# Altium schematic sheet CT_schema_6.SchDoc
size 368 x 245 mm
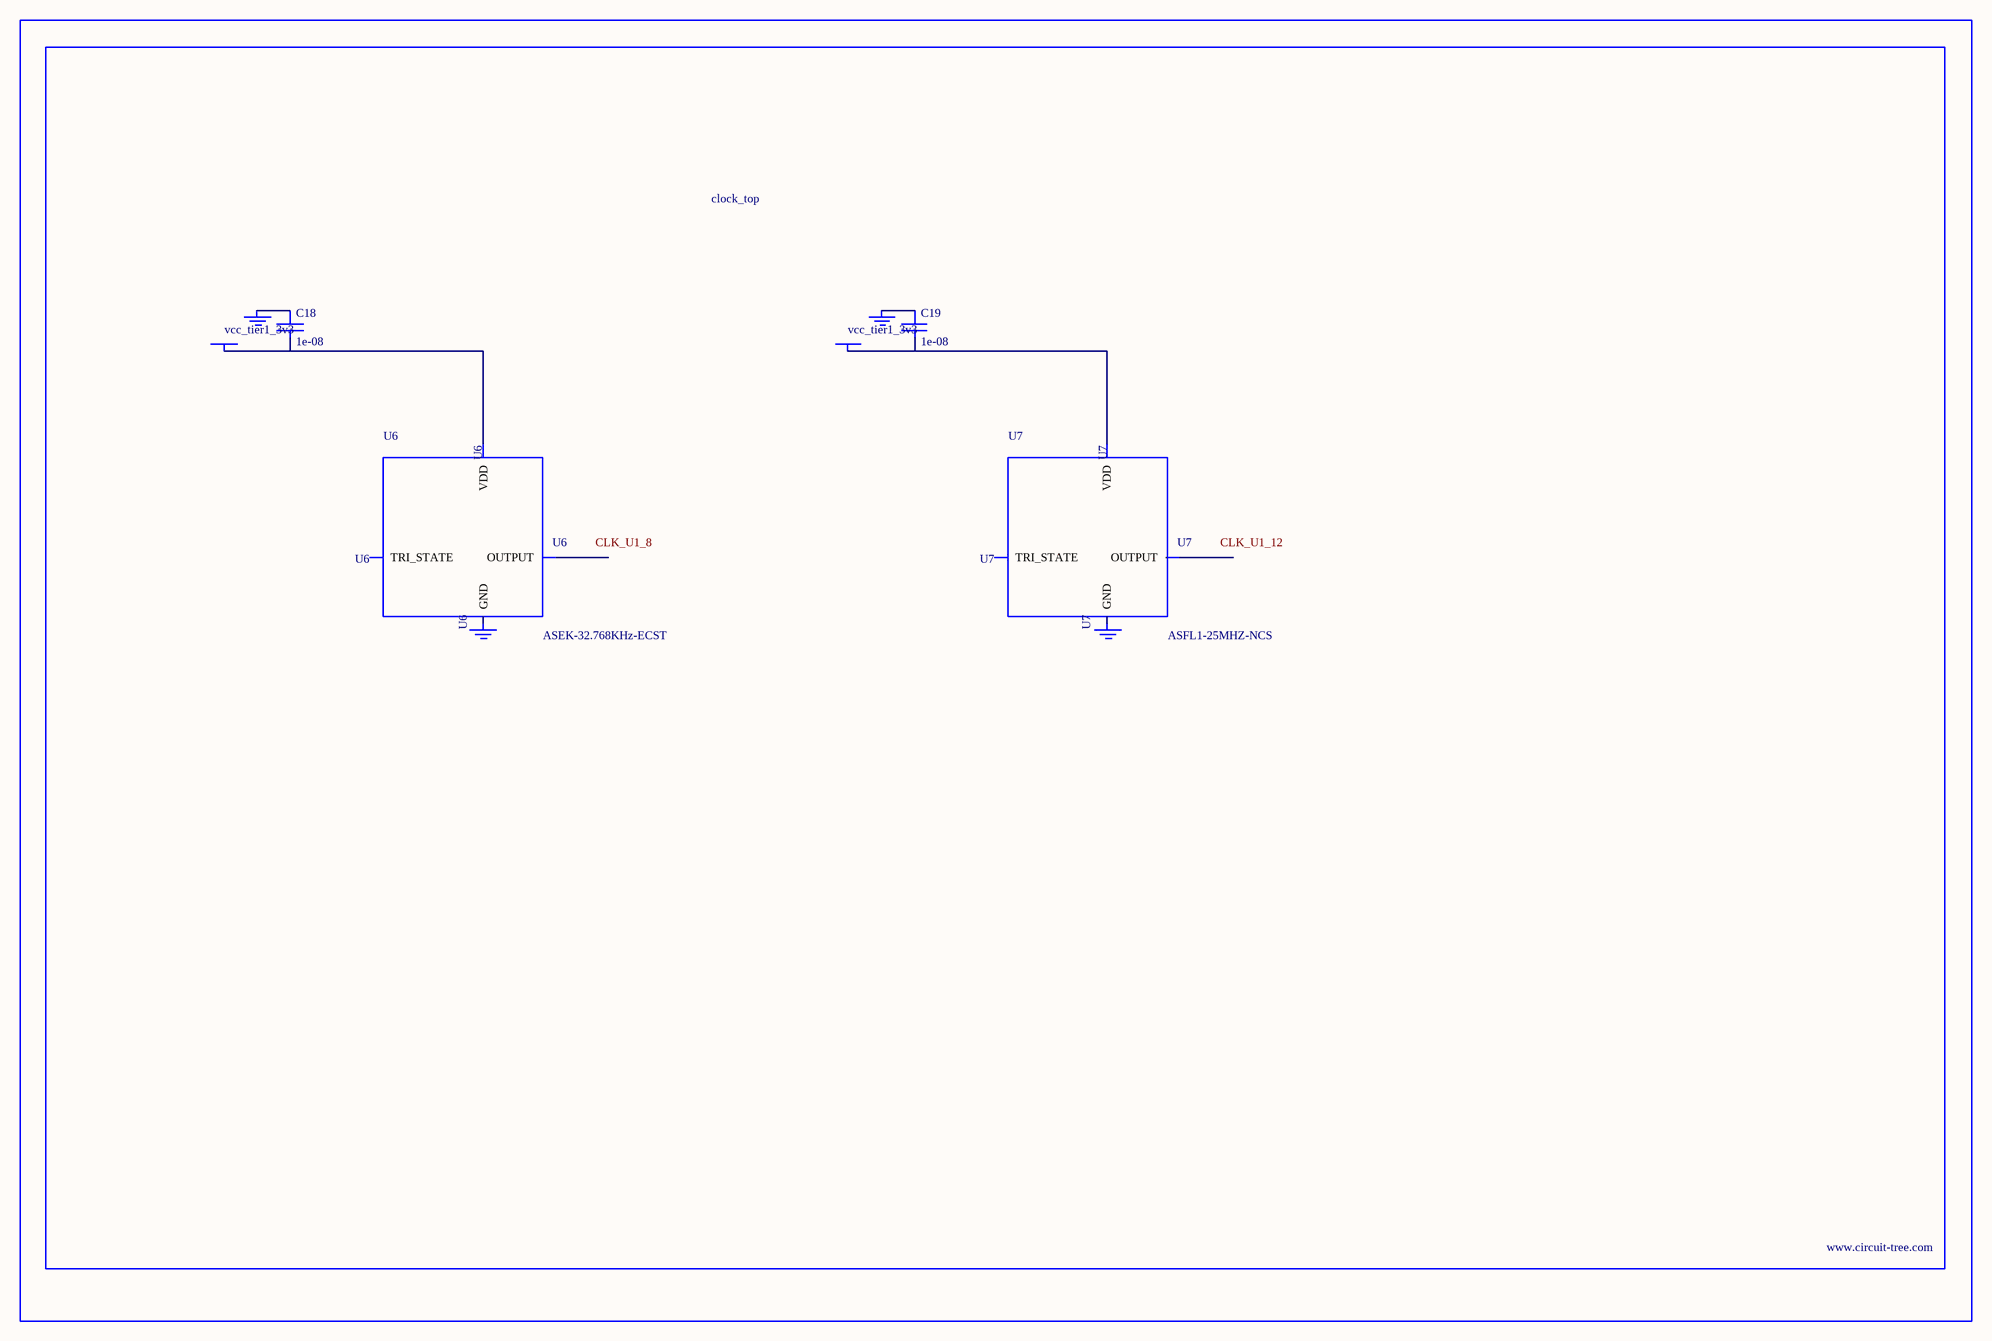
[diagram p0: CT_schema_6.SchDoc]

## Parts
BORDER5  (no value)
C18  1e-08  [C0402]
C19  1e-08  [C0402]
GND_INSTANCE_5_0  (no value)
GND_INSTANCE_5_1  (no value)
GND_INSTANCE_5_2  (no value)
GND_INSTANCE_5_3  (no value)
POWER_INSTANCE_5_0  vcc_tier1_3v3
POWER_INSTANCE_5_1  vcc_tier1_3v3
U6  ASEK-32.768KHz-ECST  [ASEK]
U7  ASFL1-25MHZ-NCS  [ASFL1]

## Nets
NetC18_1: C18.1 GND_INSTANCE_5_0.0(GND)
NetC18_2: C18.2 POWER_INSTANCE_5_0.0(PWR) U6.4(VDD)
NetC19_1: C19.1 GND_INSTANCE_5_2.0(GND)
NetC19_2: C19.2 POWER_INSTANCE_5_1.0(PWR) U7.4(VDD)

Not connected (* = marked no-connect by the designer): GND_INSTANCE_5_1 0(GND); GND_INSTANCE_5_3 0(GND); U6 1(TRI_STATE) 2(GND) 3(OUTPUT); U7 1(TRI_STATE) 2(GND) 3(OUTPUT)

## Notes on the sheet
- Labels drawn without touching a wire or pin: CLK_U1_8, CLK_U1_12

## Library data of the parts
BORDER5 = BORDER_PAGE5
C18 C19 = C0402C103K3RAC
GND_INSTANCE_5_0-GND_INSTANCE_5_3 = GND
POWER_INSTANCE_5_0 POWER_INSTANCE_5_1 = PWR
